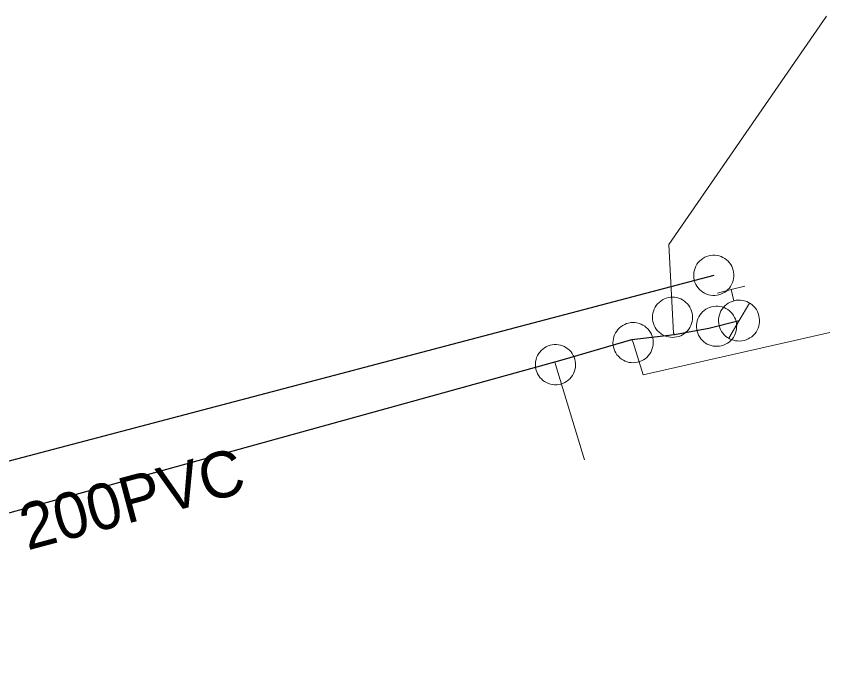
# Model space of a CAD drawing. Extents: x -741806 to -738704, y -1059275 to -1055387.
# Drawn here: x -740588.96 to -740571.26, y -1057271.49 to -1057257.53 of the extents above; entities that cross this region are included whole.
import ezdxf

# ---------------------------------------------------------------- set-up
doc = ezdxf.new("R2010")
doc.units = 0
doc.header["$LTSCALE"] = 0.4
for name, color, linetype, lineweight in [('2', 7, 'Continuous', 25), ('21', 7, 'Continuous', 13), ('3', 7, 'Continuous', 13), ('50', 7, 'Continuous', 13), ('51', 7, 'Continuous', 13), ('52', 7, 'Continuous', 25)]:
    doc.layers.add(name, color=color, linetype=linetype, lineweight=lineweight)
doc.layers.add('5', color=7, linetype='Continuous')

msp = doc.modelspace()

# ---------------------------------------------------------------- linework, layer by layer
at = {"layer": '2'}
msp.add_line((-740573.78, -1057263.169), (-740598.879, -1057269.78), dxfattribs=at)
at = {"layer": '21'}
for points in [[(-740574.636, -1057264.455), (-740574.66, -1057264.429), (-740574.761, -1057262.495), (-740571.329, -1057257.53)], [(-740575.563, -1057264.566), (-740575.537, -1057264.632), (-740575.315, -1057265.335), (-740571.256, -1057264.409)], [(-740577.24, -1057265.051), (-740577.227, -1057265.111), (-740576.596, -1057267.185)]]:
    msp.add_lwpolyline(points, dxfattribs=at)
at = {"layer": '3'}
msp.add_lwpolyline([(-740574.203, -1057263.28), (-740574.189, -1057263.322), (-740574.171, -1057263.364), (-740574.148, -1057263.405), (-740574.121, -1057263.441), (-740574.091, -1057263.475), (-740574.057, -1057263.507), (-740574.02, -1057263.533), (-740573.98, -1057263.557), (-740573.938, -1057263.575), (-740573.895, -1057263.589), (-740573.85, -1057263.599), (-740573.804, -1057263.605), (-740573.759, -1057263.604), (-740573.713, -1057263.6), (-740573.668, -1057263.591), (-740573.624, -1057263.577), (-740573.583, -1057263.558), (-740573.543, -1057263.536), (-740573.506, -1057263.509), (-740573.472, -1057263.478), (-740573.441, -1057263.444), (-740573.414, -1057263.408), (-740573.391, -1057263.368), (-740573.372, -1057263.326), (-740573.358, -1057263.282), (-740573.349, -1057263.238), (-740573.343, -1057263.193), (-740573.343, -1057263.146), (-740573.348, -1057263.101), (-740573.357, -1057263.056), (-740573.371, -1057263.013), (-740573.389, -1057262.971), (-740573.412, -1057262.931), (-740573.439, -1057262.893), (-740573.469, -1057262.86), (-740573.503, -1057262.828), (-740573.54, -1057262.802), (-740573.58, -1057262.778), (-740573.621, -1057262.76), (-740573.664, -1057262.746), (-740573.709, -1057262.736), (-740573.755, -1057262.73), (-740573.801, -1057262.73), (-740573.846, -1057262.735), (-740573.891, -1057262.744), (-740573.935, -1057262.758), (-740573.977, -1057262.776), (-740574.016, -1057262.799), (-740574.054, -1057262.827), (-740574.088, -1057262.857), (-740574.118, -1057262.891), (-740574.146, -1057262.927), (-740574.169, -1057262.967), (-740574.188, -1057263.009), (-740574.202, -1057263.053), (-740574.212, -1057263.098), (-740574.217, -1057263.142), (-740574.217, -1057263.189), (-740574.212, -1057263.234), (-740574.203, -1057263.279)], dxfattribs=at)
at = {"layer": '50'}
for p, q in [((-740573.106, -1057263.401), (-740573.403, -1057263.477)), ((-740573.702, -1057263.554), (-740573.403, -1057263.477)), ((-740573.341, -1057263.72), (-740573.403, -1057263.477)), ((-740573.228, -1057264.153), (-740573.001, -1057263.772)), ((-740573.228, -1057264.153), (-740573.456, -1057264.539))]:
    msp.add_line(p, q, dxfattribs=at)
msp.add_lwpolyline([(-740572.797, -1057264.046), (-740572.812, -1057263.999), (-740572.829, -1057263.956), (-740572.853, -1057263.915), (-740572.88, -1057263.877), (-740572.908, -1057263.843), (-740572.945, -1057263.81), (-740572.982, -1057263.784), (-740573.022, -1057263.758), (-740573.064, -1057263.738), (-740573.108, -1057263.724), (-740573.154, -1057263.713), (-740573.2, -1057263.706), (-740573.247, -1057263.707), (-740573.293, -1057263.711), (-740573.339, -1057263.72), (-740573.383, -1057263.734), (-740573.425, -1057263.75), (-740573.466, -1057263.774), (-740573.505, -1057263.802), (-740573.541, -1057263.833), (-740573.572, -1057263.866), (-740573.6, -1057263.904), (-740573.624, -1057263.944), (-740573.643, -1057263.985), (-740573.659, -1057264.03), (-740573.671, -1057264.076), (-740573.675, -1057264.121), (-740573.677, -1057264.169), (-740573.671, -1057264.215), (-740573.665, -1057264.261), (-740573.65, -1057264.307), (-740573.631, -1057264.349), (-740573.61, -1057264.388), (-740573.583, -1057264.429), (-740573.551, -1057264.463), (-740573.518, -1057264.496), (-740573.48, -1057264.522), (-740573.441, -1057264.548), (-740573.396, -1057264.568), (-740573.354, -1057264.582), (-740573.306, -1057264.592), (-740573.261, -1057264.597), (-740573.216, -1057264.6), (-740573.166, -1057264.595), (-740573.121, -1057264.587), (-740573.077, -1057264.572), (-740573.035, -1057264.553), (-740572.993, -1057264.531), (-740572.955, -1057264.505), (-740572.919, -1057264.473), (-740572.888, -1057264.44), (-740572.859, -1057264.402), (-740572.836, -1057264.363), (-740572.815, -1057264.321), (-740572.802, -1057264.276), (-740572.789, -1057264.231), (-740572.784, -1057264.184), (-740572.785, -1057264.138), (-740572.789, -1057264.091)], close=True, dxfattribs=at)
at = {"layer": '51'}
for points in [[(-740574.24, -1057264.081), (-740574.242, -1057264.036), (-740574.25, -1057263.991), (-740574.262, -1057263.946), (-740574.277, -1057263.904), (-740574.299, -1057263.863), (-740574.323, -1057263.824), (-740574.353, -1057263.789), (-740574.385, -1057263.756), (-740574.421, -1057263.728), (-740574.458, -1057263.703), (-740574.5, -1057263.682), (-740574.543, -1057263.665), (-740574.587, -1057263.653), (-740574.632, -1057263.646), (-740574.678, -1057263.644), (-740574.723, -1057263.646), (-740574.769, -1057263.653), (-740574.813, -1057263.665), (-740574.855, -1057263.682), (-740574.897, -1057263.703), (-740574.934, -1057263.728), (-740574.97, -1057263.756), (-740575.002, -1057263.789), (-740575.032, -1057263.824), (-740575.056, -1057263.863), (-740575.078, -1057263.904), (-740575.093, -1057263.946), (-740575.105, -1057263.991), (-740575.113, -1057264.036), (-740575.115, -1057264.082), (-740575.113, -1057264.127), (-740575.105, -1057264.172), (-740575.093, -1057264.217), (-740575.078, -1057264.259), (-740575.056, -1057264.3), (-740575.032, -1057264.339), (-740575.002, -1057264.374), (-740574.97, -1057264.407), (-740574.934, -1057264.435), (-740574.897, -1057264.46), (-740574.855, -1057264.481), (-740574.813, -1057264.498), (-740574.769, -1057264.509), (-740574.723, -1057264.517), (-740574.678, -1057264.519), (-740574.632, -1057264.517), (-740574.587, -1057264.509), (-740574.543, -1057264.498), (-740574.5, -1057264.481), (-740574.458, -1057264.46), (-740574.421, -1057264.435), (-740574.385, -1057264.407), (-740574.353, -1057264.374), (-740574.323, -1057264.339), (-740574.299, -1057264.3), (-740574.277, -1057264.259), (-740574.262, -1057264.217), (-740574.25, -1057264.172), (-740574.242, -1057264.127), (-740574.24, -1057264.082)], [(-740573.295, -1057264.167), (-740573.308, -1057264.124), (-740573.326, -1057264.082), (-740573.349, -1057264.042), (-740573.375, -1057264.005), (-740573.406, -1057263.97), (-740573.44, -1057263.939), (-740573.476, -1057263.912), (-740573.516, -1057263.888), (-740573.557, -1057263.87), (-740573.6, -1057263.855), (-740573.645, -1057263.845), (-740573.691, -1057263.839), (-740573.737, -1057263.839), (-740573.782, -1057263.843), (-740573.827, -1057263.853), (-740573.871, -1057263.866), (-740573.913, -1057263.884), (-740573.953, -1057263.907), (-740573.99, -1057263.934), (-740574.025, -1057263.964), (-740574.055, -1057263.998), (-740574.083, -1057264.034), (-740574.106, -1057264.074), (-740574.125, -1057264.115), (-740574.14, -1057264.159), (-740574.15, -1057264.204), (-740574.155, -1057264.249), (-740574.155, -1057264.295), (-740574.151, -1057264.341), (-740574.142, -1057264.386), (-740574.128, -1057264.429), (-740574.11, -1057264.471), (-740574.087, -1057264.511), (-740574.061, -1057264.548), (-740574.031, -1057264.582), (-740573.997, -1057264.614), (-740573.96, -1057264.641), (-740573.921, -1057264.665), (-740573.879, -1057264.683), (-740573.836, -1057264.698), (-740573.791, -1057264.708), (-740573.745, -1057264.713), (-740573.7, -1057264.713), (-740573.654, -1057264.71), (-740573.609, -1057264.7), (-740573.565, -1057264.687), (-740573.524, -1057264.668), (-740573.484, -1057264.646), (-740573.446, -1057264.619), (-740573.412, -1057264.588), (-740573.381, -1057264.555), (-740573.353, -1057264.519), (-740573.331, -1057264.479), (-740573.311, -1057264.438), (-740573.297, -1057264.394), (-740573.287, -1057264.349), (-740573.282, -1057264.304), (-740573.281, -1057264.257), (-740573.286, -1057264.212), (-740573.295, -1057264.168)], [(-740575.103, -1057264.58), (-740575.11, -1057264.536), (-740575.122, -1057264.492), (-740575.139, -1057264.448), (-740575.16, -1057264.409), (-740575.186, -1057264.37), (-740575.216, -1057264.335), (-740575.249, -1057264.303), (-740575.284, -1057264.274), (-740575.323, -1057264.251), (-740575.364, -1057264.231), (-740575.407, -1057264.215), (-740575.452, -1057264.203), (-740575.497, -1057264.196), (-740575.543, -1057264.195), (-740575.588, -1057264.198), (-740575.634, -1057264.206), (-740575.678, -1057264.218), (-740575.72, -1057264.235), (-740575.761, -1057264.257), (-740575.799, -1057264.283), (-740575.834, -1057264.312), (-740575.866, -1057264.344), (-740575.894, -1057264.381), (-740575.919, -1057264.419), (-740575.939, -1057264.461), (-740575.955, -1057264.504), (-740575.966, -1057264.547), (-740575.972, -1057264.594), (-740575.974, -1057264.639), (-740575.971, -1057264.685), (-740575.963, -1057264.729), (-740575.951, -1057264.773), (-740575.933, -1057264.817), (-740575.912, -1057264.856), (-740575.887, -1057264.895), (-740575.857, -1057264.93), (-740575.824, -1057264.962), (-740575.789, -1057264.991), (-740575.749, -1057265.014), (-740575.709, -1057265.034), (-740575.666, -1057265.05), (-740575.621, -1057265.062), (-740575.576, -1057265.068), (-740575.53, -1057265.07), (-740575.484, -1057265.067), (-740575.439, -1057265.059), (-740575.395, -1057265.046), (-740575.353, -1057265.03), (-740575.312, -1057265.008), (-740575.274, -1057264.982), (-740575.239, -1057264.953), (-740575.207, -1057264.921), (-740575.179, -1057264.884), (-740575.154, -1057264.846), (-740575.134, -1057264.804), (-740575.118, -1057264.761), (-740575.107, -1057264.718), (-740575.101, -1057264.671), (-740575.099, -1057264.626), (-740575.102, -1057264.581)], [(-740576.805, -1057264.995), (-740576.819, -1057264.952), (-740576.838, -1057264.91), (-740576.861, -1057264.87), (-740576.888, -1057264.834), (-740576.919, -1057264.8), (-740576.954, -1057264.769), (-740576.991, -1057264.743), (-740577.031, -1057264.72), (-740577.073, -1057264.702), (-740577.116, -1057264.688), (-740577.161, -1057264.679), (-740577.207, -1057264.674), (-740577.253, -1057264.674), (-740577.298, -1057264.679), (-740577.343, -1057264.69), (-740577.387, -1057264.704), (-740577.428, -1057264.723), (-740577.467, -1057264.746), (-740577.504, -1057264.774), (-740577.538, -1057264.805), (-740577.568, -1057264.839), (-740577.595, -1057264.876), (-740577.617, -1057264.916), (-740577.636, -1057264.958), (-740577.65, -1057265.002), (-740577.659, -1057265.047), (-740577.663, -1057265.092), (-740577.663, -1057265.138), (-740577.658, -1057265.184), (-740577.648, -1057265.229), (-740577.633, -1057265.271), (-740577.615, -1057265.313), (-740577.591, -1057265.353), (-740577.564, -1057265.389), (-740577.533, -1057265.423), (-740577.499, -1057265.454), (-740577.462, -1057265.48), (-740577.422, -1057265.503), (-740577.38, -1057265.521), (-740577.336, -1057265.535), (-740577.291, -1057265.544), (-740577.245, -1057265.549), (-740577.2, -1057265.548), (-740577.155, -1057265.543), (-740577.11, -1057265.533), (-740577.066, -1057265.519), (-740577.025, -1057265.499), (-740576.985, -1057265.477), (-740576.948, -1057265.449), (-740576.914, -1057265.418), (-740576.884, -1057265.384), (-740576.857, -1057265.347), (-740576.835, -1057265.307), (-740576.816, -1057265.265), (-740576.803, -1057265.221), (-740576.793, -1057265.176), (-740576.789, -1057265.131), (-740576.79, -1057265.085), (-740576.795, -1057265.039), (-740576.805, -1057264.996)]]:
    msp.add_lwpolyline(points, dxfattribs=at)
at = {"layer": '52'}
msp.add_lwpolyline([(-740599.789, -1057271.49), (-740599.544, -1057271.217), (-740577.079, -1057265.007), (-740575.563, -1057264.566), (-740574.636, -1057264.455), (-740573.886, -1057264.318), (-740573.23, -1057264.149)], dxfattribs=at)

# ---------------------------------------------------------------- texts
at = {"layer": '5'}
msp.add_text('200PVC', height=1, rotation=15, dxfattribs=at).set_placement((-740588.724, -1057269.158))

doc.saveas('drawing.dxf')
